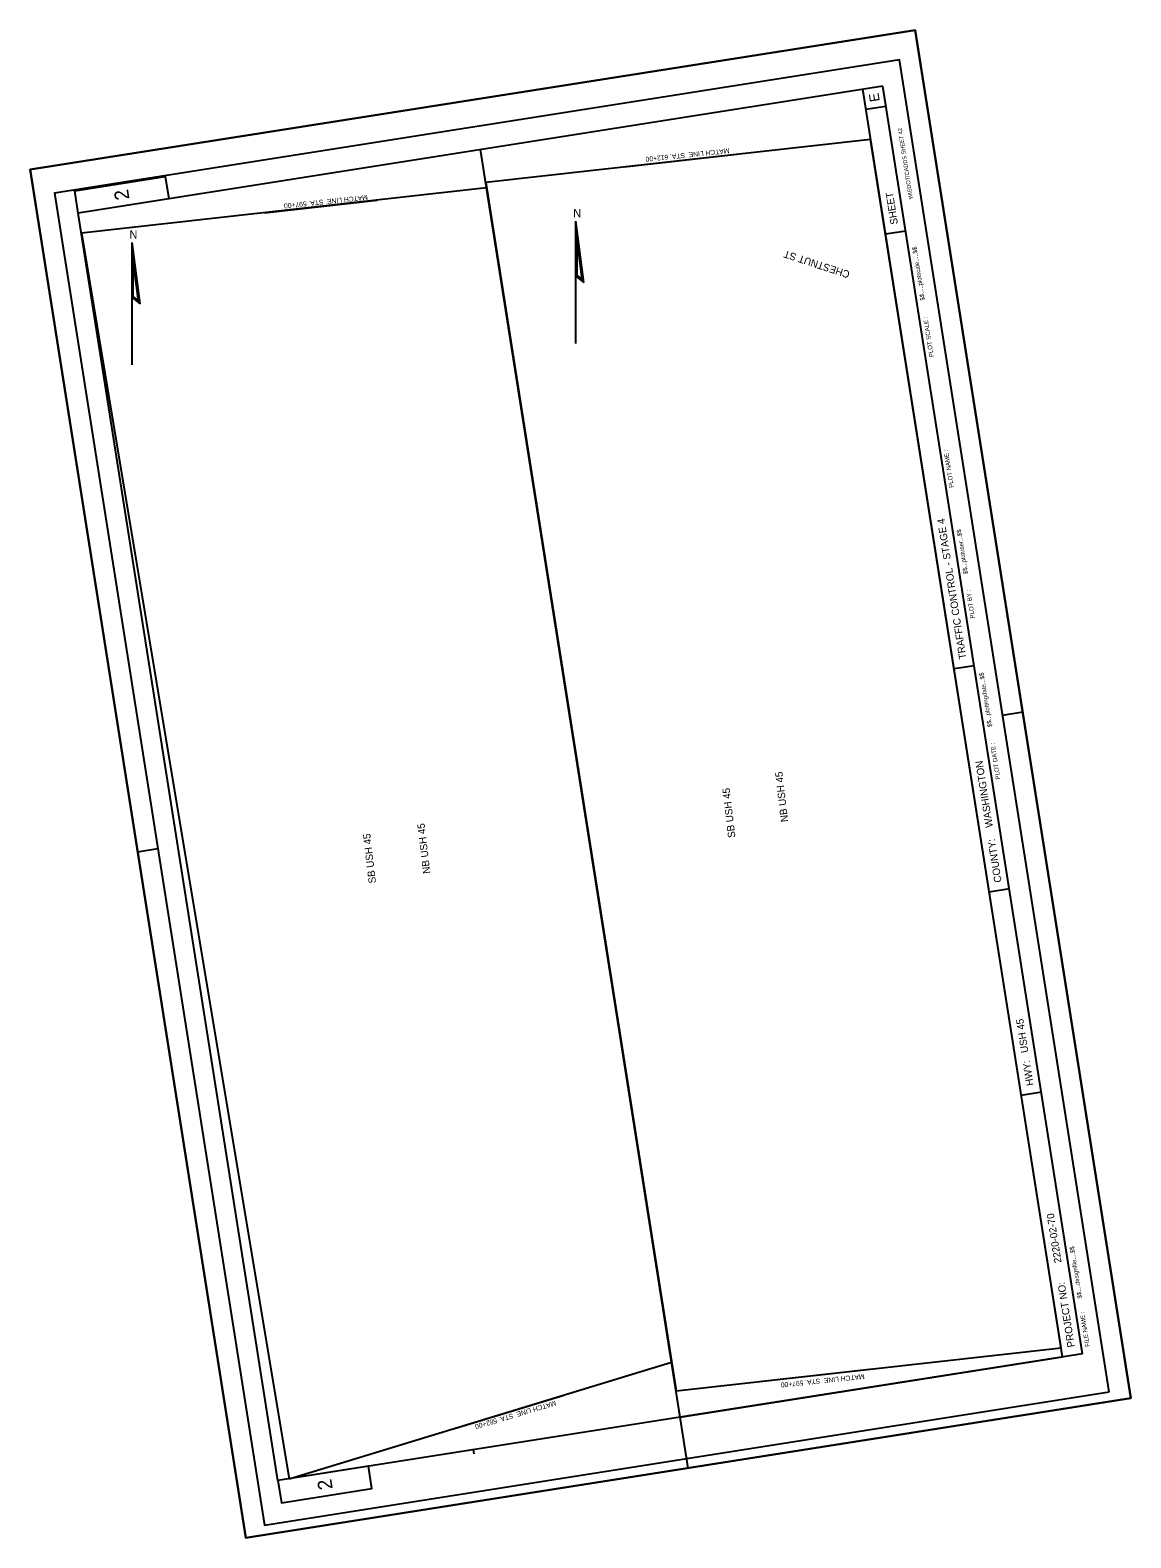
# Model space of a CAD drawing. Extents: x 355657 to 357008, y 180289 to 182140.
import ezdxf

# ---------------------------------------------------------------- set-up
doc = ezdxf.new("R2010")
doc.units = 0
for name, color, linetype in [('Default', 7, 'Continuous'), ('P_ALI_20', 7, 'Continuous'), ('P_ALI_200_Sta', 7, 'Continuous'), ('P_ALI_20_PIData', 7, 'Continuous'), ('P_ALI_20_Tic', 7, 'Continuous'), ('P_ALI_50_Equation', 7, 'Continuous'), ('P_ALI_50_PIData', 7, 'Continuous'), ('P_ALI_50_Tic', 7, 'Continuous')]:
    doc.layers.add(name, color=color, linetype=linetype)

msp = doc.modelspace()

# ---------------------------------------------------------------- linework, layer by layer
msp.add_lwpolyline([(355921.7, 180289.2), (355657, 181968.5), (356743.6, 182139.7), (357008.3, 180460.5), (355921.7, 180289.2)])
at = {"layer": 'Default'}
for points in [[(356450.1, 180469.7), (356922.6, 180522.4), (356688.8, 182005.7), (356216.3, 181952.9)], [(356450.1, 180469.7), (356922.6, 180522.4), (356688.8, 182005.7), (356216.3, 181952.9)], [(356450.1, 180469.7), (356922.6, 180522.4), (356688.8, 182005.7), (356216.3, 181952.9)], [(355975, 180361.6), (356444.5, 180504.7), (356217.4, 181946), (355720, 181890.5)], [(355975, 180361.6), (356444.5, 180504.7), (356217.4, 181946), (355720, 181890.5)], [(355975, 180361.6), (356444.5, 180504.7), (356217.4, 181946), (355720, 181890.5)]]:
    msp.add_lwpolyline(points, close=True, dxfattribs=at)
at = {"layer": 'P_ALI_20'}
for p, q in [((356743.6, 182139.7), (356694.2, 182131.9)), ((356751.4, 182090.3), (356743.6, 182139.7)), ((356703.9, 182070.9), (355716, 181915.3)), ((356924.4, 180511.3), (356679.2, 182067.1)), ((356949.1, 180515.2), (356703.9, 182070.9)), ((356707.7, 182046.2), (356683.1, 182042.4)), ((356455.2, 180437.3), (356210, 181993.1)), ((355706.4, 181976.2), (355657, 181968.5)), ((355664.8, 181919.1), (355657, 181968.5)), ((355961.3, 180359.5), (355716, 181915.3)), ((356731.9, 181893.1), (356707.2, 181889.2)), ((356816, 181359.7), (356791.3, 181355.8)), ((356879.5, 181277.9), (356871.7, 181327.2)), ((356875.6, 181302.6), (356850.9, 181298.7)), ((355792.9, 181106.6), (355785.1, 181156)), ((355789, 181131.3), (355813.7, 181135.2)), ((356859.2, 181085.6), (356834.5, 181081.7)), ((356898.5, 180836.2), (356873.8, 180832.3)), ((356949.1, 180515.2), (355961.3, 180359.5)), ((357008.3, 180460.5), (357000.5, 180509.8)), ((356449.3, 180474.3), (356449.3, 180474.3)), ((357008.3, 180460.5), (356958.9, 180452.7)), ((356465, 180374.8), (356455.2, 180437.3)), ((356200.8, 180397.2), (356201.6, 180392.3)), ((356489.7, 180378.7), (356440.3, 180370.9)), ((355921.7, 180289.2), (355913.9, 180338.6)), ((355971.1, 180297), (355921.7, 180289.2))]:
    msp.add_line(p, q, dxfattribs=at)
for points in [[(355716, 181915.3), (355711.8, 181942.4), (355822.9, 181959.9), (355827.2, 181932.8)], [(355961.3, 180359.5), (355965.5, 180332.3), (356076.7, 180349.8), (356072.4, 180377)]]:
    msp.add_lwpolyline(points, close=True, dxfattribs=at)
at = {"layer": 'P_ALI_200_Sta'}
msp.add_lwpolyline([(356455.2, 180437.3), (356924.4, 180511.3)], dxfattribs=at)
at = {"layer": 'P_ALI_20_PIData'}
for p, q in [((356336.9, 181830.2), (356326.9, 181905.2)), ((356326.9, 181837.7), (356326.9, 181905.2)), ((356327.6, 181838), (356327.6, 181893.9)), ((356335.9, 181831.8), (356327.6, 181893.9)), ((355792.1, 181804), (355782.1, 181879)), ((355782.1, 181811.5), (355782.1, 181879)), ((356328.4, 181838.4), (356328.4, 181882.6)), ((356334.9, 181833.5), (356328.4, 181882.6)), ((355782.8, 181811.9), (355782.8, 181867.7)), ((355791.1, 181805.7), (355782.8, 181867.7)), ((355783.6, 181812.3), (355783.6, 181856.4)), ((355790.1, 181807.4), (355783.6, 181856.4)), ((356326.9, 181837.7), (356336.9, 181830.2)), ((356326.9, 181755.2), (356326.9, 181837.7)), ((356327.1, 181755.2), (356327.1, 181837.5)), ((356327.6, 181838), (356335.9, 181831.8)), ((356328.4, 181838.4), (356334.9, 181833.5)), ((355782.1, 181811.5), (355792.1, 181804)), ((355782.1, 181729), (355782.1, 181811.5)), ((355782.3, 181729), (355782.3, 181811.3)), ((355782.8, 181811.9), (355791.1, 181805.7)), ((355783.6, 181812.3), (355790.1, 181807.4))]:
    msp.add_line(p, q, dxfattribs=at)
for points in [[(356326.9, 181905.1), (356326.9, 181905.1)], [(355782.1, 181879), (355782.1, 181879)]]:
    msp.add_lwpolyline(points, dxfattribs=at)
at = {"layer": 'P_ALI_20_Tic'}
msp.add_lwpolyline([(355921.7, 180289.2), (355657, 181968.5), (356743.6, 182139.7), (357008.3, 180460.5)], close=True, dxfattribs=at)
at = {"layer": 'P_ALI_50_Equation'}
for p, q in [((356386.3, 181971.9), (356524.8, 181987.4)), ((355944.8, 181915.6), (356083.2, 181931)), ((356552.6, 180481.2), (356691.1, 180496.6)), ((356177.8, 180423.4), (356311, 180464))]:
    msp.add_line(p, q, dxfattribs=at)
at = {"layer": 'P_ALI_50_Tic'}
for points in [[(357008.3, 180460.5), (356743.6, 182139.7), (355657, 181968.5), (355921.7, 180289.2)], [(356981.7, 180468.4), (356724.1, 182103.2), (355686.9, 181939.8), (355944.6, 180304.9)]]:
    msp.add_lwpolyline(points, close=True, dxfattribs=at)

# ---------------------------------------------------------------- texts
at = {"layer": 'P_ALI_20'}
for s, height, p in [('E', 12, (356700.1, 182052.7)), ('WISDOT/CADDS SHEET 42', 5, (356740.8, 181932.7)), ('2', 17.5, (355779.1, 181932.5)), ('SHEET ', 9, (356722.4, 181901.8)), ('$$.....plotscale.....$$', 5.4, (356755.4, 181808.3)), ('PLOT SCALE : ', 5.4, (356766.3, 181738.9)), ('PLOT NAME :                      ', 5.4, (356791.1, 181578.5)), ('TRAFFIC CONTROL - STAGE 4', 9, (356806.5, 181368.4)), ('$$...plotuser...$$', 5.4, (356808.3, 181472.4)), ('PLOT BY :', 5.4, (356816.9, 181418.1)), ('$$...plottingdate...$$', 5.4, (356837.9, 181284.7)), ('PLOT DATE :', 5.4, (356848, 181220.5)), (' WASHINGTON', 9, (356839.6, 181158.4)), ('COUNTY:', 9, (356849.7, 181094.2)), (' USH 45', 9, (356883.2, 180881.9)), ('HWY:', 9, (356889, 180844.8)), (' 2220-02-70', 9, (356923.8, 180624)), ('$$....designfile....$$', 5.4, (356948.4, 180583.4)), ('PROJECT NO:', 9, (356939.6, 180523.8)), ('FILE NAME :', 5.4, (356957.8, 180524.1)), ('2', 17.5, (356028.6, 180349.5))]:
    msp.add_text(s, height=height, rotation=98.957, dxfattribs=at).set_placement(p)
at = {"layer": 'P_ALI_20_PIData'}
for p in [(356323.8, 181910.1), (355779, 181884)]:
    msp.add_text('N', height=10, dxfattribs=at).set_placement(p)
at = {"layer": 'P_ALI_50_PIData'}
for s, height, rotation, p in [('MATCH LINE  STA. 612+00', 6, 185.9528, (356515.1, 181994.8)), ('MATCH LINE  STA. 597+00', 6, 185.9528, (356071.2, 181937.5)), ('CHESTNUT ST', 9, 161.8804, (356664.1, 181843.5)), ('NB USH 45', 9, 96.7083, (356587.7, 181168.3)), ('SB USH 45', 9, 96.7083, (356522.9, 181148.9)), ('SB USH 45', 9, 96.7083, (356081.7, 181093)), ('NB USH 45', 9, 96.7083, (356148.4, 181104.9)), ('MATCH LINE  STA. 597+00', 6, 185.9528, (356681.1, 180490.4)), ('MATCH LINE  STA. 582+00', 6, 196.5344, (356301.7, 180457.7))]:
    msp.add_text(s, height=height, rotation=rotation, dxfattribs=at).set_placement(p)

doc.saveas('drawing.dxf')
